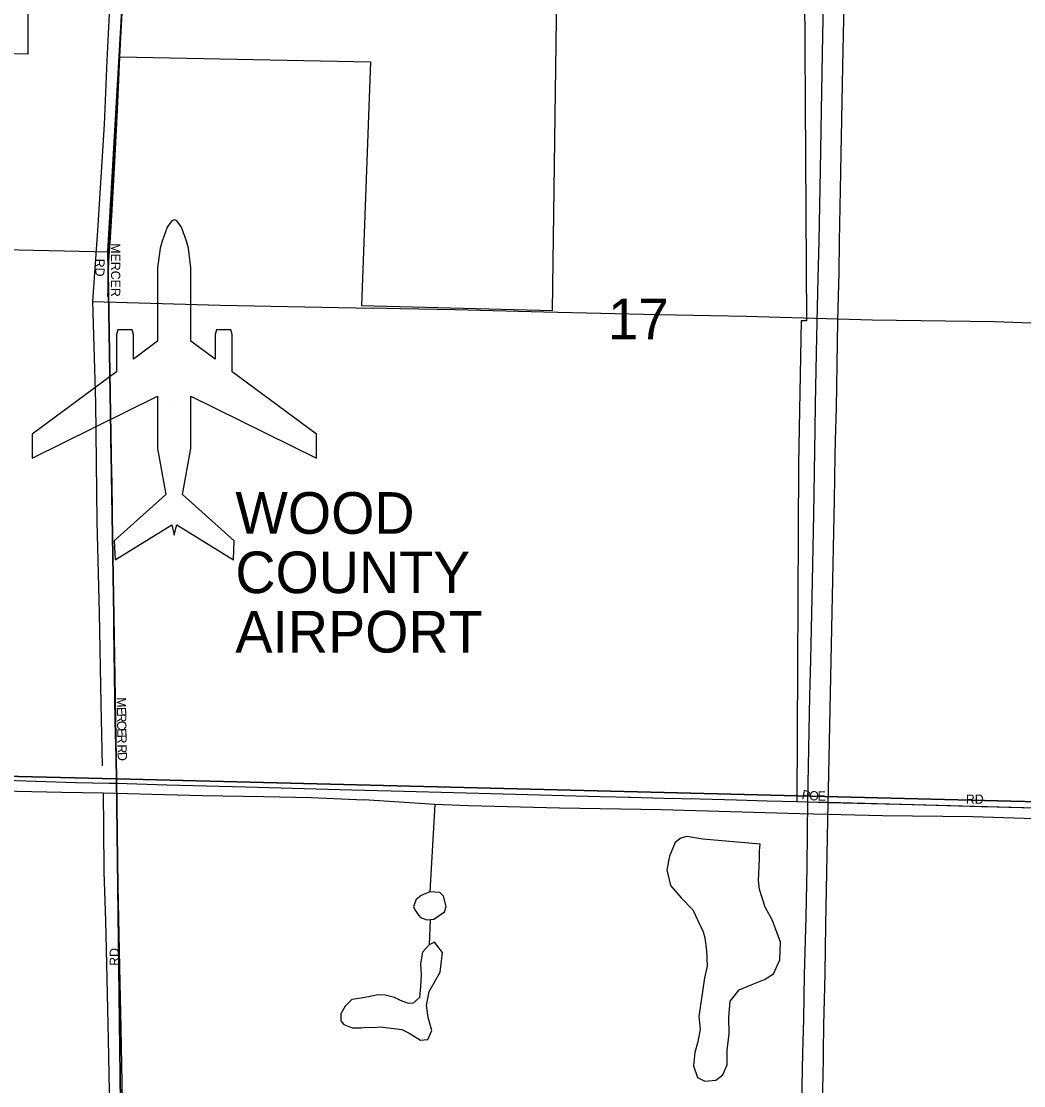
# Model space of a CAD drawing. Extents: x 1443599 to 1910620, y 1028088 to 1361369.
# Drawn here: x 1657763 to 1663185, y 1233606 to 1239361 of the extents above; entities that cross this region are included whole.
import ezdxf

# ---------------------------------------------------------------- set-up
doc = ezdxf.new("R2010")
doc.units = 0
for name, color, linetype in [('GM_X_Airport_Class_2', 7, 'Continuous'), ('GM_X_Airport_Location_Class_2', 7, 'Continuous'), ('GM_X_Airport_Text_Class_2', 7, 'Continuous'), ('GM_X_City_Street', 7, 'Continuous'), ('GM_X_City_Street_Text', 7, 'Continuous'), ('GM_X_Corporation', 7, 'Continuous'), ('GM_X_County_Road', 7, 'Continuous'), ('GM_X_Interstate_Route', 7, 'Continuous'), ('GM_X_Minor_Lake', 7, 'Continuous'), ('GM_X_Minor_River', 7, 'Continuous'), ('GM_X_Section', 7, 'Continuous'), ('GM_X_Section_Text', 7, 'Continuous'), ('GM_X_Township_Road', 7, 'Continuous')]:
    doc.layers.add(name, color=color, linetype=linetype)

msp = doc.modelspace()

# ---------------------------------------------------------------- linework, layer by layer
at = {"layer": 'GM_X_Airport_Class_2'}
msp.add_lwpolyline([(1658278.2, 1237466), (1657821.8, 1237128.5), (1657821.8, 1236999), (1658500.8, 1237333.6), (1658500.8, 1237051.9), (1658545.9, 1236802.5), (1658266.5, 1236551.9), (1658270.9, 1236448.7), (1658576.9, 1236638.3), (1658591, 1236582.8), (1658605.1, 1236638.3), (1658911.2, 1236448.7), (1658915.6, 1236551.9), (1658636.2, 1236802.5), (1658681.2, 1237051.9), (1658681.2, 1237333.6), (1659360.2, 1236999), (1659360.2, 1237128.5), (1658903.8, 1237466), (1658903.8, 1237667.5), (1658896.8, 1237692), (1658819, 1237692), (1658811.9, 1237667.5), (1658811.9, 1237534), (1658681.2, 1237630.6), (1658681.2, 1237630.6), (1658681.2, 1238028.5), (1658668.1, 1238133.7), (1658657.1, 1238171.2), (1658630.2, 1238247.8), (1658605.2, 1238281.9), (1658591, 1238287.8), (1658576.8, 1238281.9), (1658551.9, 1238247.8), (1658524.9, 1238171.2), (1658514, 1238133.7), (1658500.8, 1238028.5), (1658500.8, 1237630.6), (1658370.1, 1237534), (1658370.1, 1237667.5), (1658363, 1237692), (1658285.3, 1237692), (1658278.2, 1237667.5)], close=True, dxfattribs=at)
at = {"layer": 'GM_X_Airport_Location_Class_2'}
msp.add_line((1658591, 1237305.2), (1658591, 1237305.2), dxfattribs=at)
at = {"layer": 'GM_X_City_Street'}
for points in [[(1658232.3, 1237872.9), (1658232.9, 1237911), (1658233.7, 1237968.8), (1658237.6, 1238064.6), (1658241.1, 1238114.3)], [(1658280.2, 1235240.6), (1658278, 1235296.3), (1658275.9, 1235381.3), (1658271.1, 1235574.5), (1658263.3, 1236081.8), (1658261.5, 1236343.7), (1658258.8, 1236556.5), (1658254.4, 1236867.4), (1658247.7, 1237080.1)], [(1655644.5, 1235313.7), (1655794.9, 1235309.6), (1656237.6, 1235296.9), (1656516.4, 1235290), (1656844.3, 1235279.5), (1657155.9, 1235271.6), (1657680.7, 1235257.9), (1658057.8, 1235245.5), (1658238.2, 1235241.8), (1658280.2, 1235240.6)], [(1658280.2, 1235240.6), (1658549.8, 1235233.3), (1658976.1, 1235221), (1659550.1, 1235205.2), (1659763.2, 1235200.2), (1660304.4, 1235186.2), (1660894.8, 1235170), (1660980.2, 1235168), (1661050.1, 1235166.5)], [(1658303.2, 1233918.8), (1658298.6, 1234162.4), (1658293.2, 1234425.4), (1658286.3, 1234770.5), (1658280.2, 1235240.6)], [(1661050.1, 1235166.5), (1661058.8, 1235166.3), (1661239.1, 1235160.7), (1661435.8, 1235156.2), (1661632.5, 1235150.9), (1661797.9, 1235146.6), (1661957.6, 1235142.3)], [(1661957.6, 1235142.3), (1662017.4, 1235140.2), (1662128.3, 1235137.3), (1662285.3, 1235133.1), (1662514.7, 1235128.1), (1662711.1, 1235122.3), (1662956.9, 1235115.6), (1662978.6, 1235115.1)], [(1658315.8, 1233300.2), (1658311.1, 1233521.5), (1658303.3, 1233916), (1658303.2, 1233918.8)]]:
    msp.add_lwpolyline(points, dxfattribs=at)
at = {"layer": 'GM_X_Corporation'}
for points in [[(1657802.5, 1240493.9), (1657799.4, 1239182.4), (1657517.1, 1239190), (1657503.8, 1238131.2), (1658241.1, 1238114.3), (1658279.2, 1238800.6), (1658296.3, 1239168.7), (1659652.7, 1239141.6), (1659603.5, 1237825.1), (1660637, 1237796.9), (1660673.2, 1240424.8)], [(1661994.3, 1240400.4), (1662009.5, 1237741), (1661981.5, 1237742), (1661967.9, 1236966.1), (1661957.6, 1235142.4), (1662017.4, 1235140.8), (1662128.3, 1235138.4), (1663515, 1235101.2)]]:
    msp.add_lwpolyline(points, dxfattribs=at)
at = {"layer": 'GM_X_County_Road'}
msp.add_lwpolyline([(1662978.6, 1235115.1), (1663104.3, 1235111.8), (1663530.3, 1235100.8), (1663649.8, 1235094.5)], dxfattribs=at)
at = {"layer": 'GM_X_Interstate_Route'}
for points in [[(1662129.7, 1235205.9), (1662161.3, 1236776), (1662163.4, 1236890.8), (1662166.1, 1237009), (1662167.9, 1237094.3), (1662171.9, 1237271.5), (1662180.6, 1237740.9), (1662183.7, 1237875.4), (1662186.3, 1238000.1), (1662189.4, 1238170.8), (1662195.9, 1238544.9), (1662198.1, 1238650), (1662199.4, 1238735.3), (1662203.1, 1238925.6), (1662206.9, 1239116), (1662208.9, 1239201.4), (1662216.3, 1239545.9), (1662219.9, 1239762.5), (1662221, 1239841.3), (1662222.8, 1239949.6), (1662225.5, 1240087.5), (1662230.8, 1240307.4), (1662232.5, 1240393.1)], [(1661968.2, 1232615.2), (1661988.9, 1233696), (1661990.5, 1233781.3), (1661995.2, 1233965.1), (1662000.2, 1234204.8), (1662008.3, 1234516.6), (1662014.6, 1234789), (1662016.6, 1234976.3), (1662017.4, 1235140.2), (1662022, 1235333.7), (1662028.8, 1235711.2), (1662033.3, 1235908.1), (1662041.3, 1236242.8), (1662049.2, 1236695.8), (1662057.5, 1237152), (1662059.7, 1237289.9), (1662067, 1237657.4), (1662073.5, 1237972.5), (1662078.2, 1238172.7), (1662085.8, 1238556.7), (1662092.3, 1238878.4), (1662099.2, 1239285.4), (1662108.2, 1239712)], [(1662084.1, 1232843.6), (1662084.8, 1232887.1), (1662086.5, 1232988.9), (1662090.8, 1233212.2), (1662093.7, 1233350), (1662098.3, 1233583.1), (1662100.1, 1233671.8), (1662101.6, 1233744), (1662102.4, 1233786.7), (1662105, 1233934.4), (1662109.2, 1234138), (1662110.6, 1234213.4), (1662115.5, 1234476.1), (1662128.3, 1235137.3), (1662129.7, 1235205.9)]]:
    msp.add_lwpolyline(points, dxfattribs=at)
at = {"layer": 'GM_X_Minor_Lake'}
for p, q in [((1659891.8, 1234557.3), (1659912.8, 1234525.4)), ((1661458.9, 1234188.9), (1661428.8, 1233979))]:
    msp.add_line(p, q, dxfattribs=at)
for points in [[(1661428.8, 1233979), (1661434.9, 1233910.6), (1661423, 1233842.6), (1661407.3, 1233784.9), (1661399.2, 1233712.8), (1661421.5, 1233649.9), (1661461, 1233630.8), (1661519.3, 1233635.1), (1661558.2, 1233664.1), (1661581.8, 1233717.6), (1661582, 1233797.9), (1661592.6, 1233886), (1661591.1, 1233974.3), (1661597.6, 1234062.5), (1661645.4, 1234123.3), (1661710.3, 1234151.6), (1661783.3, 1234179.6), (1661832.3, 1234210.4), (1661866.5, 1234285.7), (1661869.2, 1234382), (1661826.4, 1234499.6), (1661786.4, 1234571), (1661757, 1234666.2), (1661750.4, 1234714.6), (1661755.7, 1234832.9), (1661756.9, 1234875), (1661760, 1234911.1), (1661450.1, 1234938), (1661362.3, 1234952.6), (1661330, 1234943.4), (1661299.3, 1234920.2), (1661269.1, 1234846.8), (1661255, 1234772.9), (1661274.6, 1234688.1), (1661332.9, 1234622.1), (1661395.1, 1234556.1), (1661451.9, 1234438.1), (1661461, 1234405.7), (1661469.1, 1234337.2), (1661472.7, 1234252.8), (1661458.9, 1234188.9)], [(1659912.8, 1234525.4), (1659922.9, 1234515.9), (1659956.6, 1234502.9), (1659994.8, 1234505.9), (1660052, 1234546.4), (1660060.8, 1234574.2), (1660046.4, 1234630.9), (1660026.9, 1234649.5), (1659972.9, 1234653.1), (1659926.3, 1234634.3), (1659899.6, 1234613), (1659884.5, 1234575.3), (1659891.8, 1234557.3)], [(1659602.4, 1233918), (1659631.4, 1233922), (1659671.5, 1233920.9), (1659705.6, 1233923.9), (1659749.6, 1233918.6), (1659821.5, 1233908.6), (1659861, 1233889.4), (1659922.1, 1233851.5), (1659962.3, 1233856.3), (1659983.7, 1233903.9), (1659963.6, 1233974.7), (1659955.4, 1234039.2), (1659969.6, 1234115.1), (1660028.7, 1234219.8), (1660041.8, 1234325.8), (1659999.2, 1234381.3), (1659968.8, 1234368.1), (1659933.6, 1234326.9), (1659921.8, 1234265), (1659926.1, 1234204.7), (1659922.3, 1234142.6), (1659916.6, 1234082.5), (1659883.6, 1234051.3), (1659857.5, 1234050.1), (1659813.9, 1234065.4), (1659782.3, 1234082.3), (1659731.8, 1234095.3), (1659694.5, 1234096.9), (1659650.2, 1234087.3), (1659601.4, 1234078.6)], [(1659601.4, 1234078.6), (1659551.2, 1234071.5), (1659514.5, 1234036.1), (1659491.7, 1233994.3), (1659490.9, 1233956.2), (1659508.6, 1233935.8), (1659552.3, 1233919), (1659580.4, 1233918.4), (1659602.4, 1233918)]]:
    msp.add_lwpolyline(points, dxfattribs=at)
at = {"layer": 'GM_X_Minor_River'}
for points in [[(1658380.4, 1243393.4), (1658375.1, 1242584.8), (1658339.6, 1241768.7), (1658320.8, 1241098.7), (1658293.7, 1240408.9), (1658254, 1239691.1), (1658225.6, 1239149.8), (1658211, 1238802.9), (1658176.1, 1238229.5), (1658148.8, 1237846.7), (1658164.4, 1237298.6), (1658172.2, 1236656.2), (1658184.8, 1236162.2), (1658193.5, 1235670.4), (1658201.1, 1235335.1)], [(1658148.8, 1237846.7), (1658839.4, 1237825.8), (1659663.1, 1237809.5)], [(1672708.6, 1237576.7), (1671965.4, 1237588), (1671194.4, 1237612.1), (1670461.3, 1237625.1), (1669715.8, 1237626.4), (1669223.1, 1237638.5), (1668972.4, 1237635.6), (1668226.7, 1237628.9), (1667398.7, 1237620.5), (1666598.6, 1237607.2), (1665887.6, 1237623.6), (1664762.4, 1237665.8), (1664115.7, 1237688.4), (1663654.3, 1237713.4), (1663627.5, 1237716.4), (1663475.2, 1237718.8), (1663026.7, 1237735.6), (1662365.6, 1237744.5), (1661684.7, 1237764), (1661206, 1237773.7), (1660589, 1237787.3), (1660110.4, 1237801), (1659813.9, 1237805.5), (1659663.1, 1237809.5)], [(1654394.1, 1235274), (1654860.5, 1235261.2), (1655196.9, 1235252.9), (1655585.3, 1235239.6), (1655953.6, 1235228.7), (1656308.1, 1235224.1), (1656680.6, 1235219.1), (1656983, 1235219.4), (1657299.3, 1235207.5), (1657657.7, 1235200.8), (1657982.1, 1235192.7), (1658206.3, 1235188.5), (1658468.6, 1235181.6), (1658742.9, 1235174.4), (1659073.3, 1235170.2), (1659333.6, 1235163.3), (1659615.8, 1235152)], [(1658206.3, 1235188.5), (1658208.8, 1235001.8), (1658210.3, 1234762.9), (1658219.3, 1234497.9), (1658225.3, 1234184.7), (1658233, 1233853.4), (1658240, 1233480), (1658239.9, 1233158.9), (1658252.7, 1232885.7), (1658256.5, 1232664.8)], [(1663631.5, 1235036.2), (1662910.6, 1235058.8), (1662421.7, 1235064.8), (1661975.1, 1235075.6), (1661224.1, 1235097.1), (1660675.2, 1235106.7), (1660182.5, 1235118.8), (1660000.3, 1235126.1), (1659615.8, 1235152)], [(1660000.3, 1235126.1), (1659972.9, 1234653.1)], [(1659975.4, 1234504.4), (1659968.8, 1234368.1)]]:
    msp.add_lwpolyline(points, dxfattribs=at)
at = {"layer": 'GM_X_Section'}
for points in [[(1652630.6, 1240616.9), (1658369.4, 1240479.4), (1658232.2, 1238116.1), (1658278.7, 1235264.2), (1652604.1, 1235400.9), (1652601.3, 1235495)], [(1658369.4, 1240479.4), (1663692.8, 1240369.8), (1663695.4, 1235129.4), (1658278.7, 1235264.2), (1658232.2, 1238116.1)], [(1652604.1, 1235400.9), (1658278.7, 1235264.2), (1658343.9, 1230008.1), (1652586.7, 1230105.6), (1652586.1, 1230207.6)], [(1658278.7, 1235264.2), (1663695.4, 1235129.4), (1663596.4, 1229891.8), (1658343.9, 1230008.1)]]:
    msp.add_lwpolyline(points, close=True, dxfattribs=at)
at = {"layer": 'GM_X_Township_Road'}
for points in [[(1658296.3, 1239168.7), (1658303.4, 1239307.9), (1658311.4, 1239438.9), (1658318, 1239570.1), (1658325.7, 1239717.6), (1658336.1, 1239914.3), (1658360.4, 1240356.7), (1658365.5, 1240476.8)], [(1658241.1, 1238114.3), (1658246.2, 1238192.2), (1658255.6, 1238339.2), (1658269.6, 1238600.6), (1658281.4, 1238845.8), (1658290.4, 1239041.8), (1658296.3, 1239168.7)]]:
    msp.add_lwpolyline(points, dxfattribs=at)

# ---------------------------------------------------------------- texts
at = {"layer": 'GM_X_Airport_Text_Class_2'}
for s, p in [('WOOD', (1658921.2, 1236590)), ('COUNTY', (1658921.2, 1236268.8)), ('AIRPORT', (1658921.2, 1235947.6))]:
    msp.add_text(s, height=225, rotation=0.00001, dxfattribs=at).set_placement(p)
at = {"layer": 'GM_X_City_Street_Text'}
for s, rotation, p in [('MERCER', 270, (1658248.6, 1238160.9)), ('RD', 270, (1658163.6, 1238077.3)), ('M', 270.89262, (1658279.4, 1235705.8)), ('E', 270.87427, (1658280.3, 1235653)), ('R', 270.88455, (1658280.8, 1235617.8)), ('C', 270.87431, (1658281.4, 1235578.2)), ('E', 270.88648, (1658282, 1235538.6)), ('R', 270.8986, (1658282.6, 1235503.4)), ('R', 270.86081, (1658283.4, 1235450.7)), ('D', 273.71516, (1658284.1, 1235408.4)), ('P', 349.8638, (1661981.8, 1235156)), ('O', 358.13503, (1662024.3, 1235149)), ('E', 0.04553, (1662070.1, 1235147.5)), ('RD', 0.00001, (1662872.4, 1235129.9)), ('RD', 90, (1658291.4, 1234253.7))]:
    msp.add_text(s, height=50, rotation=rotation, dxfattribs=at).set_placement(p)
at = {"layer": 'GM_X_Section_Text'}
msp.add_text('17', height=221, rotation=0.00001, dxfattribs=at).set_placement((1660936.4, 1237640.4))

doc.saveas('drawing.dxf')
